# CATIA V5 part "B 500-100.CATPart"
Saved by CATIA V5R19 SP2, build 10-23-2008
Part number: B 500-100
Bounding box of the stored display mesh (mm): x -18.951 to 18.951, y -18.952 to 18.952, z 0 to 250
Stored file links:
  C:\Users\Bora\Desktop\3D Katı model\B serisi\B 500\B 500-100.CATPart
  C:\Program Files\Dassault Systemes\B19\intel_a\reffiles\standard\MetricThickPitch.txt
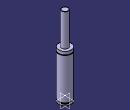
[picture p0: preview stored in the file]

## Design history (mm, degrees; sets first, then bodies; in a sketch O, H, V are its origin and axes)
Body1 (main body)
  Sketch1 on yz-plane, origin (0, 0, 0), H (0, 1, 0), V (0, 0, 1)
    point P1 (19, 138.5)
    point P4 (19, 136.5)
    point P7 (19, 138.5)
    point P8 (19, 136.5)
    point P9 (10, 249)
    point P11 (10, 249)
    line L1 (19, 138.5) -> (19, 148)
    line L2 (19, 7.5) -> (19, 136.5)
    line L3 (16.5, 7.5) -> (16.5, 4)
    arc A1 centre (19, 137.5) radius 1 from (19, 138.5) to (19, 136.5) ccw
    arc A2 centre (9, 249) radius 1 from (10, 249) to (9, 250) ccw
    line L4 (10, 249) -> (10, 148)
    line L5 (19, 0) -> (19, 4)
    line L6 (9, 250) -> (0, 250)
    point P15 (0, 250)
    line L7 (10, 148) -> (19, 148)
    line L8 (0, 0) -> (19, 0)
    line L9 (16.5, 7.5) -> (19, 7.5)
    line L10 (16.5, 4) -> (19, 4)
    coincidence: P15 V, P1 P7, P4 P8, P9 P11
    tangency: L6 A2
    horizontal: L7 H, L8 H, L9 H, L10 H
  Shaft1: profile Sketch1, axis Sketch1.V, angle 360
  Sketch2 on face of Shaft1 from Sketch1.L8, origin (0, 0, 0), H (1, 0, 0), V (0, -1, 0)
    point P1 (0, 0)
  Hole1: placed by Sketch2, at (0, 0, 0) direction (0, 0, 1), diameter 6.647, depth 7, threaded "M8", thread diameter 8, thread depth 7, pitch 1.25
